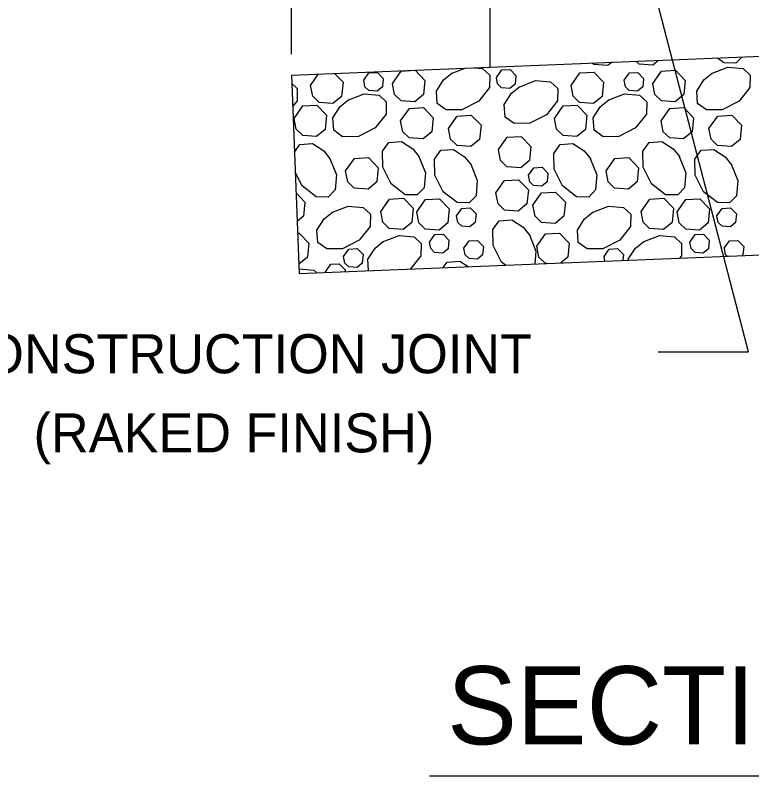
# Model space of a CAD drawing. Extents: x 2084213 to 2099800, y 976677 to 981262.
# Drawn here: x 2084499.7 to 2084685.2, y 979910.6 to 980102.2 of the extents above; entities that cross this region are included whole.
import ezdxf

# ---------------------------------------------------------------- set-up
doc = ezdxf.new("R2010")
doc.units = 0
doc.layers.add('1', color=7, linetype='Continuous')

msp = doc.modelspace()

# ---------------------------------------------------------------- linework, layer by layer
at = {"layer": '1'}
for p, q in [((2084619.23, 980223.01), (2084619.23, 980089.1)), ((2084684.41, 980017.39), (2084647.99, 980156.9)), ((2084569.27, 980092.34), (2084569.27, 980136.03)), ((2084619.23, 980089.1), (2084843.77, 980098.08)), ((2084569.27, 980087.1), (2084619.23, 980089.1)), ((2084569.27, 980087.1), (2084571.26, 980037.14)), ((2084571.26, 980037.14), (2084843.77, 980048.04)), ((2084661.64, 980017.39), (2084684.41, 980017.39)), ((2084604.02, 979910.62), (2084821.6, 979910.62))]:
    msp.add_line(p, q, dxfattribs=at)
for points in [[(2084661.75, 980090.8), (2084660.32, 980089.61), (2084656.84, 980089.86), (2084656.1, 980090.57)], [(2084682.67, 980091.64), (2084681.22, 980090.12), (2084678.15, 980090.18), (2084676.59, 980091.39)], [(2084615.41, 980088.95), (2084617.42, 980088.77), (2084619.23, 980087.06), (2084619.17, 980083.98), (2084616.44, 980080.49), (2084612.21, 980078.38), (2084608.23, 980078.31), (2084605.99, 980079.9), (2084605.77, 980083.07), (2084607.59, 980085.91), (2084609.68, 980087.57)], [(2084649.96, 980090.33), (2084648.94, 980089.48), (2084645.46, 980089.73), (2084645.05, 980090.13)], [(2084675.09, 980087.46), (2084679.21, 980089.1), (2084683, 980088.77), (2084684.8, 980087.06), (2084684.75, 980083.98), (2084682.01, 980080.49), (2084677.79, 980078.38), (2084673.81, 980078.31), (2084671.56, 980079.9), (2084671.35, 980083.07), (2084673.17, 980085.91), (2084675.25, 980087.57)], [(2084580.1, 980087.53), (2084582.27, 980085.28), (2084581.92, 980081.72), (2084579.74, 980079.91), (2084576.26, 980080.17), (2084574.63, 980081.75), (2084574.1, 980084.48)], [(2084574.1, 980084.48), (2084576.13, 980087.38)], [(2084587.48, 980085.77), (2084588.8, 980087.65), (2084590.92, 980087.77), (2084592.38, 980086.25), (2084592.17, 980084.12), (2084590.87, 980083.03), (2084588.78, 980083.18), (2084587.8, 980084.13), (2084587.48, 980085.77)], [(2084594.71, 980084.96), (2084596.91, 980088.09), (2084600.43, 980088.29), (2084602.88, 980085.76), (2084602.53, 980082.2), (2084600.35, 980080.39), (2084596.88, 980080.64), (2084595.24, 980082.23), (2084594.71, 980084.96)], [(2084609.51, 980087.46), (2084613.01, 980088.85)], [(2084620.89, 980086.49), (2084622.22, 980088.38), (2084624.33, 980088.5), (2084625.8, 980086.97), (2084625.59, 980084.84), (2084624.28, 980083.75), (2084622.19, 980083.9), (2084621.21, 980084.86), (2084620.89, 980086.49)], [(2084639.68, 980084.48), (2084641.88, 980087.62), (2084645.4, 980087.82), (2084647.85, 980085.28), (2084647.5, 980081.72), (2084645.32, 980079.91), (2084641.84, 980080.17), (2084640.21, 980081.75), (2084639.68, 980084.48)], [(2084653.06, 980085.77), (2084654.38, 980087.65), (2084656.49, 980087.77), (2084657.96, 980086.25), (2084657.75, 980084.12), (2084656.45, 980083.03), (2084654.36, 980083.18), (2084653.38, 980084.13), (2084653.06, 980085.77)], [(2084660.29, 980084.96), (2084662.49, 980088.09), (2084666.01, 980088.29), (2084668.46, 980085.76), (2084668.11, 980082.2), (2084665.93, 980080.39), (2084662.46, 980080.64), (2084660.82, 980082.23), (2084660.29, 980084.96)], [(2084626.61, 980084.08), (2084630.73, 980085.71), (2084634.52, 980085.39), (2084636.33, 980083.67), (2084636.27, 980080.6), (2084633.53, 980077.1), (2084629.31, 980074.99), (2084625.33, 980074.92), (2084623.09, 980076.51), (2084622.87, 980079.68), (2084624.69, 980082.52), (2084626.77, 980084.18)], [(2084569.35, 980085), (2084570.75, 980083.67), (2084570.69, 980080.6), (2084569.58, 980079.18)], [(2084583.44, 980080.74), (2084587.57, 980082.38), (2084591.36, 980082.05), (2084593.16, 980080.34), (2084593.11, 980077.26), (2084590.37, 980073.77), (2084586.14, 980071.65), (2084582.16, 980071.58), (2084579.92, 980073.18), (2084579.71, 980076.35), (2084581.53, 980079.18), (2084583.61, 980080.85)], [(2084649.02, 980080.74), (2084653.15, 980082.38), (2084656.94, 980082.05), (2084658.74, 980080.34), (2084658.68, 980077.26), (2084655.95, 980073.77), (2084651.72, 980071.65), (2084647.74, 980071.58), (2084645.5, 980073.18), (2084645.29, 980076.35), (2084647.11, 980079.18), (2084649.19, 980080.85)], [(2084569.95, 980076.18), (2084572.15, 980079.32), (2084575.67, 980079.52), (2084578.12, 980076.98), (2084577.77, 980073.42), (2084575.59, 980071.61), (2084572.11, 980071.87), (2084570.48, 980073.45), (2084569.95, 980076.18)], [(2084635.52, 980076.18), (2084637.73, 980079.32), (2084641.25, 980079.52), (2084643.7, 980076.98), (2084643.35, 980073.42), (2084641.17, 980071.61), (2084637.69, 980071.87), (2084636.06, 980073.45), (2084635.53, 980076.18)], [(2084596.78, 980075.56), (2084598.99, 980078.7), (2084602.51, 980078.9), (2084604.96, 980076.36), (2084604.6, 980072.81), (2084602.43, 980071), (2084598.95, 980071.25), (2084597.32, 980072.83), (2084596.78, 980075.56)], [(2084662.36, 980075.56), (2084664.57, 980078.7), (2084668.09, 980078.9), (2084670.54, 980076.36), (2084670.18, 980072.81), (2084668.01, 980071), (2084664.53, 980071.25), (2084662.9, 980072.83), (2084662.36, 980075.56)], [(2084608.84, 980073.64), (2084611.05, 980076.78), (2084614.57, 980076.98), (2084617.02, 980074.44), (2084616.66, 980070.89), (2084614.49, 980069.07), (2084611.01, 980069.33), (2084609.37, 980070.91), (2084608.84, 980073.64)], [(2084674.42, 980073.64), (2084676.63, 980076.78), (2084680.15, 980076.98), (2084682.59, 980074.44), (2084682.24, 980070.89), (2084680.07, 980069.07), (2084676.59, 980069.33), (2084674.95, 980070.91), (2084674.42, 980073.64)], [(2084621.38, 980068.31), (2084623.59, 980071.44), (2084627.11, 980071.64), (2084629.56, 980069.11), (2084629.2, 980065.55), (2084627.03, 980063.74), (2084623.55, 980063.99), (2084621.91, 980065.58), (2084621.38, 980068.31)], [(2084570.04, 980067.71), (2084571.39, 980069.61), (2084574.56, 980069.82), (2084577.4, 980068.01), (2084579.06, 980065.92)], [(2084601.37, 980066.62), (2084603.01, 980062.5), (2084602.68, 980058.71), (2084600.97, 980056.91), (2084597.89, 980056.96), (2084594.4, 980059.7), (2084592.28, 980063.92), (2084592.21, 980067.91), (2084593.81, 980070.15), (2084596.98, 980070.36), (2084599.82, 980068.54), (2084601.48, 980066.46)], [(2084644.53, 980066.09), (2084646.17, 980061.97), (2084645.84, 980058.17), (2084644.13, 980056.37), (2084641.05, 980056.43), (2084637.56, 980059.16), (2084635.45, 980063.39), (2084635.38, 980067.37), (2084636.97, 980069.61), (2084640.14, 980069.82), (2084642.98, 980068.01), (2084644.64, 980065.92)], [(2084666.95, 980066.62), (2084668.59, 980062.5), (2084668.26, 980058.71), (2084666.55, 980056.91), (2084663.47, 980056.96), (2084659.98, 980059.7), (2084657.86, 980063.92), (2084657.79, 980067.91), (2084659.39, 980070.15), (2084662.56, 980070.36), (2084665.4, 980068.54), (2084667.06, 980066.46)], [(2084614.45, 980064.62), (2084616.08, 980060.5), (2084615.76, 980056.71), (2084614.05, 980054.9), (2084610.97, 980054.96), (2084607.47, 980057.7), (2084605.36, 980061.92), (2084605.29, 980065.9), (2084606.88, 980068.15), (2084610.06, 980068.36), (2084612.89, 980066.54), (2084614.56, 980064.46)], [(2084680.03, 980064.62), (2084681.66, 980060.5), (2084681.34, 980056.71), (2084679.62, 980054.9), (2084676.55, 980054.96), (2084673.05, 980057.7), (2084670.94, 980061.92), (2084670.87, 980065.9), (2084672.46, 980068.15), (2084675.63, 980068.36), (2084678.47, 980066.54), (2084680.13, 980064.46)], [(2084578.95, 980066.09), (2084580.59, 980061.97), (2084580.26, 980058.17), (2084578.55, 980056.37), (2084575.48, 980056.43), (2084571.98, 980059.16), (2084570.24, 980062.64)], [(2084582.92, 980062.97), (2084585.12, 980066.11), (2084588.64, 980066.31), (2084591.09, 980063.77), (2084590.74, 980060.21), (2084588.56, 980058.4), (2084585.09, 980058.65), (2084583.45, 980060.24), (2084582.92, 980062.97)], [(2084648.5, 980062.97), (2084650.7, 980066.11), (2084654.22, 980066.31), (2084656.67, 980063.77), (2084656.32, 980060.21), (2084654.14, 980058.4), (2084650.67, 980058.65), (2084649.03, 980060.24), (2084648.5, 980062.97)], [(2084628.96, 980061.88), (2084630.28, 980063.76), (2084632.4, 980063.88), (2084633.86, 980062.36), (2084633.65, 980060.22), (2084632.35, 980059.14), (2084630.26, 980059.29), (2084629.28, 980060.24), (2084628.96, 980061.88)], [(2084620.76, 980057.41), (2084622.97, 980060.55), (2084626.49, 980060.75), (2084628.94, 980058.21), (2084628.58, 980054.65), (2084626.41, 980052.84), (2084622.93, 980053.1), (2084621.3, 980054.68), (2084620.77, 980057.41)], [(2084570.45, 980057.4), (2084572.68, 980055.1), (2084572.33, 980051.54), (2084570.74, 980050.22)], [(2084630.08, 980054.3), (2084632.29, 980057.43), (2084635.81, 980057.63), (2084638.26, 980055.1), (2084637.9, 980051.54), (2084635.73, 980049.73), (2084632.25, 980049.98), (2084630.62, 980051.57), (2084630.09, 980054.29)], [(2084591.75, 980052.74), (2084593.95, 980055.88), (2084597.47, 980056.08), (2084599.92, 980053.54), (2084599.57, 980049.99), (2084597.39, 980048.18), (2084593.91, 980048.43), (2084592.28, 980050.01), (2084591.75, 980052.74)], [(2084600.82, 980052.61), (2084603.02, 980055.74), (2084606.55, 980055.95), (2084608.99, 980053.41), (2084608.64, 980049.85), (2084606.46, 980048.04), (2084602.99, 980048.29), (2084601.35, 980049.88), (2084600.82, 980052.61)], [(2084657.32, 980052.74), (2084659.53, 980055.88), (2084663.05, 980056.08), (2084665.5, 980053.54), (2084665.14, 980049.99), (2084662.97, 980048.18), (2084659.49, 980048.43), (2084657.86, 980050.01), (2084657.33, 980052.74)], [(2084666.4, 980052.61), (2084668.6, 980055.74), (2084672.12, 980055.95), (2084674.57, 980053.41), (2084674.22, 980049.85), (2084672.04, 980048.04), (2084668.57, 980048.29), (2084666.93, 980049.88), (2084666.4, 980052.61)], [(2084579.44, 980052.45), (2084583.57, 980054.09), (2084587.36, 980053.76), (2084589.16, 980052.05), (2084589.1, 980048.97), (2084586.37, 980045.48), (2084582.14, 980043.37), (2084578.16, 980043.3), (2084575.92, 980044.89), (2084575.71, 980048.06), (2084577.53, 980050.9), (2084579.61, 980052.56)], [(2084610.85, 980051.64), (2084612.18, 980053.52), (2084614.29, 980053.64), (2084615.76, 980052.12), (2084615.55, 980049.99), (2084614.24, 980048.9), (2084612.16, 980049.05), (2084611.17, 980050), (2084610.85, 980051.64)], [(2084645.02, 980052.45), (2084649.15, 980054.09), (2084652.94, 980053.76), (2084654.74, 980052.05), (2084654.68, 980048.97), (2084651.95, 980045.48), (2084647.72, 980043.37), (2084643.74, 980043.3), (2084641.5, 980044.89), (2084641.29, 980048.06), (2084643.11, 980050.9), (2084645.19, 980052.56)], [(2084676.43, 980051.64), (2084677.76, 980053.52), (2084679.87, 980053.64), (2084681.34, 980052.12), (2084681.13, 980049.99), (2084679.82, 980048.9), (2084677.73, 980049.05), (2084676.75, 980050), (2084676.43, 980051.64)], [(2084623.15, 980039.22), (2084622.21, 980039.95), (2084620.1, 980044.17), (2084620.03, 980048.16), (2084621.63, 980050.4), (2084624.8, 980050.61), (2084627.63, 980048.79), (2084629.3, 980046.71)], [(2084570.86, 980047.29), (2084571.21, 980047.31), (2084573.66, 980044.77), (2084573.31, 980041.22), (2084571.17, 980039.44)], [(2084604.03, 980045.02), (2084605.35, 980046.9), (2084607.46, 980047.02), (2084608.93, 980045.5), (2084608.72, 980043.36), (2084607.41, 980042.28), (2084605.33, 980042.43), (2084604.35, 980043.38), (2084604.03, 980045.02)], [(2084629.19, 980046.88), (2084630.83, 980042.75), (2084630.55, 980039.51)], [(2084631.06, 980043.97), (2084633.27, 980047.11), (2084636.79, 980047.31), (2084639.24, 980044.77), (2084638.89, 980041.22), (2084637.15, 980039.78)], [(2084669.61, 980045.02), (2084670.93, 980046.9), (2084673.04, 980047.02), (2084674.51, 980045.5), (2084674.3, 980043.36), (2084672.99, 980042.28), (2084670.91, 980042.43), (2084669.93, 980043.38), (2084669.61, 980045.02)], [(2084588.7, 980037.84), (2084588.51, 980040.69), (2084590.33, 980043.53), (2084592.41, 980045.19)], [(2084592.24, 980045.08), (2084596.37, 980046.72), (2084600.16, 980046.39), (2084601.96, 980044.68), (2084601.9, 980041.6), (2084599.29, 980038.26)], [(2084612.71, 980043.47), (2084614.04, 980045.35), (2084616.15, 980045.47), (2084617.62, 980043.95), (2084617.41, 980041.81), (2084616.1, 980040.73), (2084614.02, 980040.88), (2084613.03, 980041.83), (2084612.72, 980043.47)], [(2084654.1, 980040.45), (2084654.09, 980040.69), (2084655.91, 980043.53), (2084657.99, 980045.19)], [(2084657.82, 980045.08), (2084661.95, 980046.72), (2084665.74, 980046.39), (2084667.54, 980044.68), (2084667.48, 980041.6), (2084666.99, 980040.97)], [(2084678.29, 980043.47), (2084679.62, 980045.35), (2084681.73, 980045.47), (2084683.2, 980043.95), (2084682.99, 980041.81), (2084682.73, 980041.6)], [(2084582.41, 980041.4), (2084583.74, 980043.28), (2084585.85, 980043.4), (2084587.32, 980041.88), (2084587.1, 980039.75), (2084585.8, 980038.66), (2084583.71, 980038.81), (2084582.73, 980039.76), (2084582.41, 980041.4)], [(2084633.58, 980039.63), (2084633.23, 980039.66), (2084631.6, 980041.24), (2084631.07, 980043.97)], [(2084647.99, 980041.4), (2084649.31, 980043.28), (2084651.43, 980043.4), (2084652.9, 980041.88), (2084652.75, 980040.4)], [(2084679.01, 980041.45), (2084678.61, 980041.83), (2084678.3, 980043.47)], [(2084648.22, 980040.22), (2084647.99, 980041.4)], [(2084577.86, 980037.57), (2084579.18, 980039.46), (2084581.3, 980039.57), (2084582.77, 980038.05), (2084582.72, 980037.6)], [(2084607.49, 980038.59), (2084608.48, 980039.99), (2084611.66, 980040.2), (2084613.78, 980038.84)], [(2084571.22, 980038.31), (2084574.94, 980037.99), (2084575.65, 980037.32)], [(2084577.89, 980037.41), (2084577.86, 980037.57)]]:
    msp.add_lwpolyline(points, dxfattribs=at)

# ---------------------------------------------------------------- texts
for s, height, p in [('CONSTRUCTION JOINT', 9.8425, (2084482.16, 980011.98)), ('(RAKED FINISH)', 9.8425, (2084504.33, 979992.06)), ('SECTION C-C', 19.685, (2084608.5, 979918.53))]:
    msp.add_text(s, height=height, dxfattribs=at).set_placement(p)

doc.saveas('drawing.dxf')
